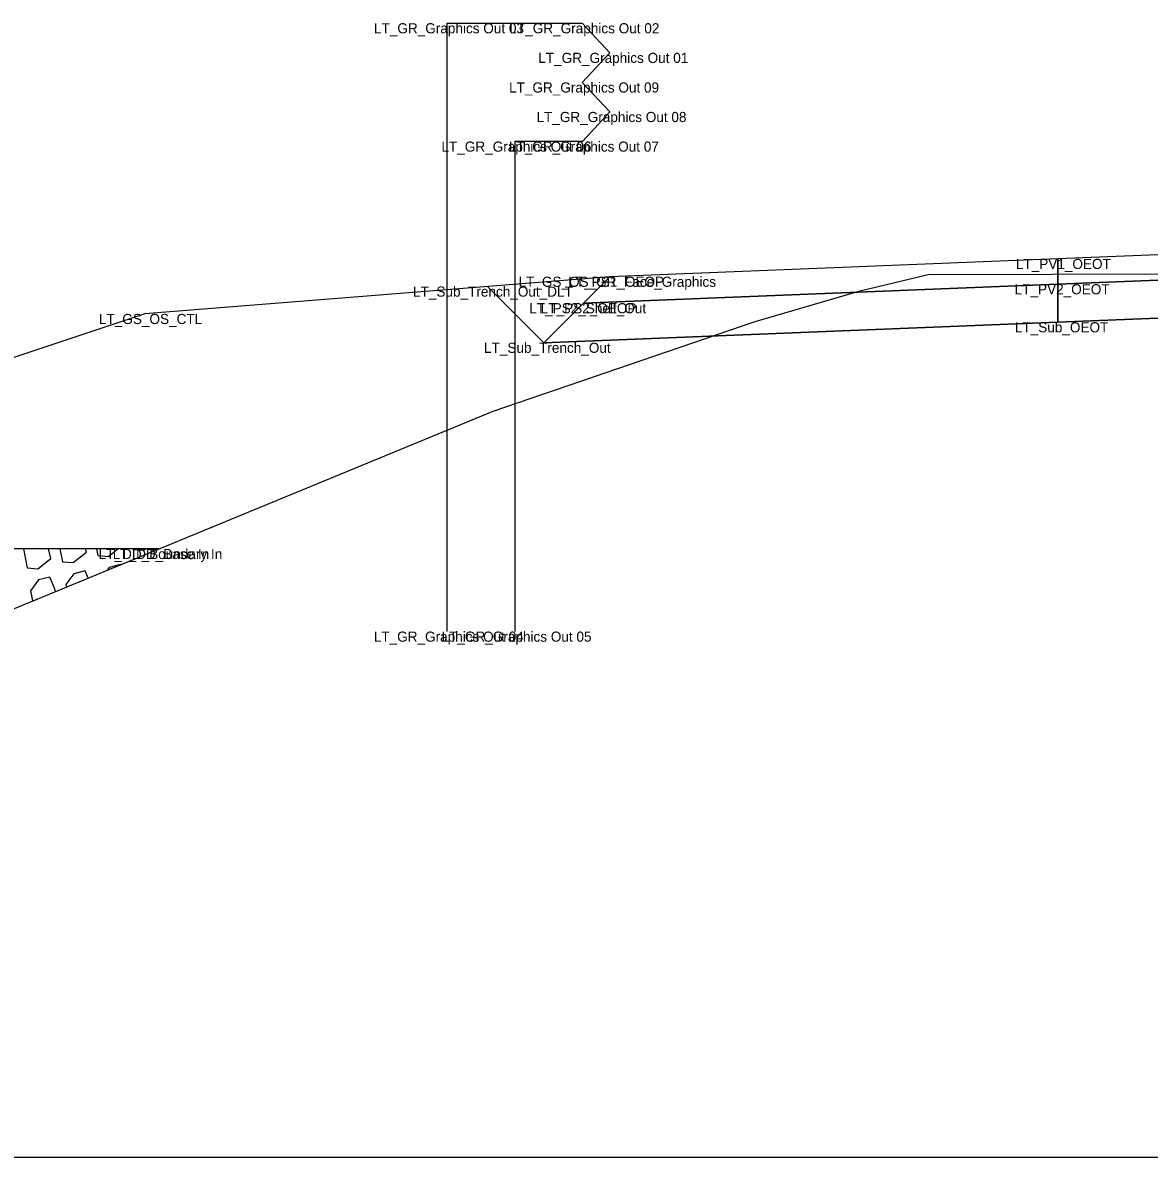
# Model space of a CAD drawing. Extents: x -26 to 203, y -10 to 20020.
# Drawn here: x 78.79 to 89.9, y 3000 to 3011.19 of the extents above; entities that cross this region are included whole.
import ezdxf

# ---------------------------------------------------------------- set-up
doc = ezdxf.new("R2010")
doc.units = 0
for name, color, linetype in [('Default', 7, 'Continuous'), ('Exist Cross Section Cell', 7, 'Continuous'), ('Exist XS Ground Line', 7, 'Continuous'), ('Old_Level_1', 7, 'Continuous'), ('Prop CMT Guardrail Graphics', 7, 'Continuous'), ('Prop CMT Pvmt Course 1', 7, 'Continuous'), ('Prop CMT Pvmt Course 2', 7, 'Continuous'), ('Prop CMT Pvmt Surface', 7, 'Continuous'), ('Prop CMT Pvmt Surface Shoulder', 7, 'Continuous'), ('Prop CMT Rip Rap Class II', 7, 'Continuous'), ('Prop CMT Shld Paved Course 1', 7, 'Continuous'), ('Prop CMT Shld Paved Course 2', 7, 'Continuous'), ('Prop CMT Slope Grass', 7, 'Continuous'), ('Prop CMT Subgrade Earthwork', 7, 'Continuous')]:
    doc.layers.add(name, color=color, linetype=linetype)

msp = doc.modelspace()

# ---------------------------------------------------------------- linework, layer by layer
at = {"layer": 'Exist Cross Section Cell'}
msp.add_line((0, 3000), (100, 3000), dxfattribs=at)
at = {"layer": 'Exist XS Ground Line'}
for p, q in [((87.053, 3008.546), (87.721, 3008.708)), ((87.721, 3008.708), (95.52, 3008.722)), ((86.015, 3008.244), (87.053, 3008.546)), ((83.434, 3007.358), (86.015, 3008.244)), ((76.464, 3004.487), (83.434, 3007.358))]:
    msp.add_line(p, q, dxfattribs=at)
at = {"layer": 'Old_Level_1'}
for p, q in [((78.801, 3006), (78.839, 3005.812)), ((79.162, 3006), (79.187, 3005.873)), ((79.523, 3006), (79.536, 3005.935)), ((79.884, 3006), (79.884, 3005.996))]:
    msp.add_line(p, q, dxfattribs=at)
for points in [[(78.839, 3005.812), (78.944, 3005.804), (79.073, 3005.907), (79.049, 3006)], [(79.187, 3005.873), (79.292, 3005.865), (79.422, 3005.969), (79.414, 3006)], [(79.536, 3005.935), (79.641, 3005.927), (79.733, 3006)], [(79.884, 3005.996), (79.99, 3005.988), (80.004, 3006)], [(79.441, 3005.713), (79.411, 3005.785), (79.298, 3005.755), (79.22, 3005.649), (79.225, 3005.624)], [(79.761, 3005.845), (79.76, 3005.846), (79.646, 3005.817), (79.626, 3005.789)], [(79.117, 3005.58), (79.108, 3005.614), (79.063, 3005.723), (78.949, 3005.694), (78.872, 3005.588), (78.892, 3005.487)]]:
    msp.add_lwpolyline(points, dxfattribs=at)
at = {"layer": 'Prop CMT Guardrail Graphics'}
for points in [[(82.979, 3005.185), (82.979, 3011.185)], [(82.979, 3011.185), (84.312, 3011.185), (84.583, 3010.893)], [(84.583, 3010.893), (84.312, 3010.601)], [(84.312, 3010.601), (84.583, 3010.31)], [(84.583, 3010.31), (84.313, 3010.018), (83.646, 3010.018)], [(83.646, 3010.018), (83.646, 3005.185)]]:
    msp.add_lwpolyline(points, dxfattribs=at)
at = {"layer": 'Prop CMT Pvmt Course 1'}
for points in [[(100, 3009.301), (89, 3008.861)], [(89, 3008.611), (100, 3009.051)], [(89, 3008.861), (89, 3008.611)]]:
    msp.add_lwpolyline(points, dxfattribs=at)
at = {"layer": 'Prop CMT Pvmt Course 2'}
for points in [[(100, 3009.051), (89, 3008.611)], [(89, 3008.236), (100, 3008.676)], [(89, 3008.611), (89, 3008.236)]]:
    msp.add_lwpolyline(points, dxfattribs=at)
at = {"layer": 'Prop CMT Pvmt Surface'}
msp.add_lwpolyline([(100, 3009.301), (89, 3008.861)], dxfattribs=at)
at = {"layer": 'Prop CMT Pvmt Surface Shoulder'}
msp.add_lwpolyline([(89, 3008.861), (84.583, 3008.685)], dxfattribs=at)
at = {"layer": 'Prop CMT Rip Rap Class II'}
for points in [[(80.137, 3006), (71.045, 3006), (64.916, 3001.914)], [(80.137, 3006), (80.137, 3006)]]:
    msp.add_lwpolyline(points, dxfattribs=at)
at = {"layer": 'Prop CMT Shld Paved Course 1'}
for points in [[(89, 3008.861), (84.583, 3008.685), (84.323, 3008.424)], [(89, 3008.611), (89, 3008.861)], [(84.323, 3008.424), (89, 3008.611)]]:
    msp.add_lwpolyline(points, dxfattribs=at)
at = {"layer": 'Prop CMT Shld Paved Course 2'}
for points in [[(89, 3008.611), (84.323, 3008.424)], [(89, 3008.236), (89, 3008.611)], [(84.323, 3008.424), (83.932, 3008.034)], [(84.323, 3008.424), (84.323, 3008.424)], [(83.932, 3008.034), (89, 3008.236)]]:
    msp.add_lwpolyline(points, dxfattribs=at)
at = {"layer": 'Prop CMT Slope Grass'}
for points in [[(84.583, 3008.685), (80, 3008.318)], [(84.583, 3008.685), (84.583, 3008.685)], [(80, 3008.318), (73.045, 3006)]]:
    msp.add_lwpolyline(points, dxfattribs=at)
at = {"layer": 'Prop CMT Subgrade Earthwork'}
for points in [[(100, 3008.676), (89, 3008.236)], [(83.932, 3008.034), (83.378, 3008.588)], [(89, 3008.236), (83.932, 3008.034)]]:
    msp.add_lwpolyline(points, dxfattribs=at)

# ---------------------------------------------------------------- texts
at = {"layer": 'Default'}
for s, p in [('LT_GR_Graphics Out 03', (82.258, 3011.085)), ('LT_GR_Graphics Out 02', (83.593, 3011.085)), ('LT_GR_Graphics Out 01', (83.878, 3010.793)), ('LT_GR_Graphics Out 09', (83.59, 3010.501)), ('LT_GR_Graphics Out 08', (83.86, 3010.21)), ('LT_GR_Graphics Out 06', (82.923, 3009.918)), ('LT_GR_Graphics Out 07', (83.588, 3009.918)), ('LT_PV1_OEOT', (88.587, 3008.761)), ('LT_GS_OS_GR_Face_Graphics', (83.683, 3008.585)), ('LT_PS1_OEOP', (84.174, 3008.585)), ('LT_Sub_Trench_Out_DLT', (82.643, 3008.488)), ('LT_PV2_OEOT', (88.575, 3008.511)), ('LT_PS2_Shelf_Out', (83.789, 3008.324)), ('LT_PS2_OEOP', (83.902, 3008.324)), ('LT_GS_OS_CTL', (79.546, 3008.218)), ('LT_Sub_OEOT', (88.577, 3008.136)), ('LT_Sub_Trench_Out', (83.343, 3007.934)), ('LT_DD_Boundary In', (79.543, 3005.9)), ('LT_DD_Base In', (79.682, 3005.9)), ('LT_GR_Graphics Out 04', (82.256, 3005.085)), ('LT_GR_Graphics Out 05', (82.924, 3005.085))]:
    msp.add_text(s, height=0.1, dxfattribs=at).set_placement(p)

doc.saveas('drawing.dxf')
